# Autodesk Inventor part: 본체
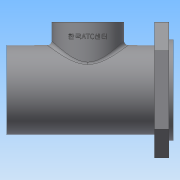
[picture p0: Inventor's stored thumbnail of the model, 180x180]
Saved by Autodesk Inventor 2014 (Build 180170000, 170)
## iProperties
Created: 2017-10
Part Number: 본체
Material: 일반
Document SubType Name: Modeling
Designer: net
Density: 1 g/cm^3
Appearance: 기본값
Author: net
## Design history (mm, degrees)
sketch "스케치1"
  geometry: L1 (-58, 47)-(58, 47); L2 (58, 47)-(58, -47); L3 (58, -47)-(-58, -47); L4 (-58, -47)-(-58, 47); L5 (-46, 20)-(-46, -20); L6 (-42, 20)-(-42, -20); L7 (-50, -20)-(-50, 20); L8 (46, 20)-(46, -20); L9 (50, 20)-(50, -20); L10 (42, -20)-(42, 20); A1 r 4 centre (-46, 20) between (-42, 20) and (-50, 20); A2 r 4 centre (-46, -20) between (-50, -20) and (-42, -20); A3 r 4 centre (46, 20) between (50, 20) and (42, 20); A4 r 4 centre (46, -20) between (42, -20) and (50, -20); 5 further points
  constraints: 24 end point, 8 point on circle, 8 tangent, 7 parallel, 4 centre point, 4 midpoint, 3 horizontal alignment, 1 equal radius, 1 horizontal, 1 perpendicular, 1 vertical alignment
  dimensions: "d0" = 116 distance of L2.end L3.end; "d1" = 94 distance of L1.end L2.end; "d2" = 46 distance of point (0, 0) point (-46, 0); "d3" = 40 distance of L5.start L5.end; "d4" = 4 radius of A1; "d7" = 46 distance of point (46, 0) point (0, 0)
extrude "돌출1" new body sketch "스케치1" distance "d5" = 10; taper "d6" = 0 deg
extrude "돌출2" cut sketch "스케치1" stored distance "d8" = 10; taper "d9" = 0 deg
chamfer "모따기1" distance "d10" = 20; stored, may be unused: second distance "d11" = 2, angle "d12" = 45 deg
sketch "스케치2"
  geometry: C1 r 31 at (0, 0); 1 further point
  constraints: 1 centre point, 1 coincident
  dimensions: "d13" = 62 diameter of C1
extrude "돌출3" join sketch "스케치2" distance "d14" = 102; taper "d15" = 0 deg
sketch "스케치3"
  geometry: C1 r 35 at (0, 0); 1 further point
  constraints: 1 centre point, 1 coincident
  dimensions: "d16" = 70 diameter of C1
extrude "돌출4" join sketch "스케치3" distance "d17" = 3; taper "d18" = 0 deg
sketch "스케치4"
  geometry: L1 (31, 0)-(31, -102) reference; L2 (-31, -102)-(31, -102) reference; L3 (35, 13)-(-35, 13) reference; L4 (0, -102)-(0, 13); L5 (0, -93)-(24, -93); L6 (24, -93)-(24, -90); L7 (24, -90)-(20, -90); L8 (20, -90)-(20, -81); L9 (20, -81)-(17.5, -81); L10 (17.5, -81)-(17.5, -77.75); L11 (17.5, -77.75)-(18.5, -77.75); L12 (18.5, -77.75)-(18.5, -76); L13 (26, -65)-(26, -27); L14 (26, -27)-(17.5, -27); L15 (17.5, -27)-(17.5, -16); L16 (17.5, -16)-(16.5, -16); L17 (16.5, -16)-(16.5, -11); L18 (16.5, -11)-(10, -11); L19 (10, -11)-(10, -8.3); L20 (10, -8.3)-(12.5, -8.3); L21 (12.5, -8.3)-(12.5, -1.7); L22 (18.5, -76)-(17.5, -76); L23 (17.5, -76)-(17.5, -65); L24 (17.5, -65)-(26, -65); L25 (12.5, -1.7)-(12.904, -1); L26 (12.904, -1)-(16, -1); L27 (16, -1)-(22, 13); 2 further points
  constraints: 48 end point, 16 parallel, 3 midpoint, 3 perpendicular, 2 point on line, 1 horizontal
  dimensions: "d19" = 3 distance of L5.end L6.end; "d20" = 9 distance of L7.end L8.end; "d21" = 48 diameter of L6 L4; "d22" = 40 diameter of L8 L4; "d23" = 9 distance between parallel lines of L2 L5; "d24" = 35 diameter of L10 L4; "d25" = 37 diameter of L12 L4; "d28" = 3.25 distance of L9.end L10.end; "d29" = 38 distance of L13.start L13.end; "d30" = 52 diameter of L13 L4; "d31" = 35 diameter of L15 L4; "d32" = 11 distance of L14.end L15.end; "d33" = 2.7 distance of L18.end L19.end; "d35" = 20 diameter of L19 L4; "d36" = 25 diameter of L21 L4; "d39" = 33 diameter of L17 L4; "d40" = 5 distance of L16.end L17.end; "d42" = 1.75 distance of L11.end L12.end; "d43" = 11 distance of L22.end L23.end; "d44" = 35 diameter of L23 L4; "d47" = 0.7 vertical distance of L21.end L25.end; "d48" = 7.3 vertical distance of L25.end L20.end; "d50" = 32 diameter of L26.end L4; "d51" = 44 diameter of L27.end L4
revolve "회전1" sketch "스케치4" stored, may be unused: angle "d52" = 90 deg
hole "구멍1" diameter "d55" = 37.129; stored, may be unused: countersink angle "d59" = 90 deg, drill point angle "d61" = 118 deg; dims "d53" = 10, "d54" = 10, "d56" = 9, "d57" = 4, "d58" = 2, "d60" = 9
node "작업 평면1"
sketch "스케치5"
  geometry: L1 (38, 0)-(-38, 0) reference; L2 (-31, -102)-(31, -102) reference; C1 r 25 at (0, -46); C2 r 16 at (0, -46); 2 further points
  constraints: 2 centre point, 1 coincident, 1 midpoint, 1 vertical alignment
  dimensions: "d63" = 50 diameter of C1; "d64" = 32 diameter of C2; "d65" = 31 distance edge to line of C1 L2
extrude "돌출5" join sketch "스케치5" stored distance "d66" = 3; taper "d67" = 0 deg
extrude "돌출6" cut sketch "스케치5" stored distance "d68" = 3; taper "d69" = 0 deg
sketch "스케치6"
  geometry: C1 r 16 at (0, 0) reference; 3 further points
  constraints: 2 horizontal alignment
  dimensions: "d70" = 41 distance of point (20.5, 0) point (-20.5, 0); "d71" = 20.5 distance of point (-20.5, 0) C1.centre
hole "구멍2" sketch "스케치6" at (-20.5, 0), (20.5, 0) diameter "d72" = 2.459; stored, may be unused: countersink angle "d76" = 90 deg, drill point angle "d78" = 118 deg; dims "d73" = 6, "d74" = 4, "d75" = 2, "d77" = 8
node "작업 평면2"
sketch "스케치7"
  geometry: L1 (16, -56)-(78, -56) reference; L2 (0, -25)-(0, 25) reference; 2 further points
  constraints: 1 other
  dimensions: "d79" = 56 distance from line of L1 point (10, 0); "d80" = 10 distance from line of point (10, 0) L2
feature "엠보싱1" sketch "스케치7" dims "d0" = 116, "d1" = 94, "d2" = 46, "d3" = 40, "d4" = 4, "d7" = 46, "d81" = 0.5, "d82" = 0
fillet "모깎기1" dims "d83" = 0.3
fillet "모깎기2" dims "d84" = 0.3
fillet "모깎기3" dims "d85" = 3
fillet "모깎기4" dims "d86" = 3
fillet "모깎기5" dims "d87" = 3
chamfer "모따기2" distance "d88" = 1; stored, may be unused: second distance "d89" = 2, angle "d90" = 45 deg
node "솔리드1"
other parameters: "d62" = 47
